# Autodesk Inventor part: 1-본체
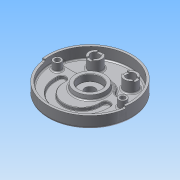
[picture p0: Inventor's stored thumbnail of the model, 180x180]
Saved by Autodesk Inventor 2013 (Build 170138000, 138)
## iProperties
Created: 2015-06
Part Number: 1-본체
Material: 알루미늄 6061
Document SubType Name: Modeling
Designer: Administrator
Density: 2.71 g/cm^3
Mass: 1076.47 g
Surface Area: 1039.69 cm^2
Volume: 397.221 cm^3
Author: Administrator
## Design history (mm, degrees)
sketch "스케치1"
  geometry: C1 r 95 at (0, 0); 1 further point
  constraints: 1 centre point, 1 coincident
  dimensions: "d0" = 190 diameter of C1
extrude "돌출1" new body sketch "스케치1" distance "d2" = 32; taper "d3" = 0 deg
sketch "스케치2"
  geometry: C1 r 95 at (0, 0) reference; C2 r 90 at (0, 0)
  constraints: 1 centre point, 1 coincident
  dimensions: "d4" = 180 diameter of C2
extrude "돌출2" cut sketch "스케치2" distance "d6" = 18; taper "d7" = 0 deg
sketch "스케치3"
  geometry: L1 (-95, 0)-(95, 0); L2 (0, 0)-(-94.075, -13.221); L3 (0, 0)-(94.075, -13.221); C1 r 90 at (0, 0) reference; A1 r 95 centre (0, 0) between (-95, 0) and (95, 0) reference; A2 r 90 centre (0, 0) between (-89.124, -12.526) and (89.124, -12.526); A3 r 95 centre (0, 0) between (-94.075, -13.221) and (94.075, -13.221)
  constraints: 8 point on circle, 6 end point, 3 coincident, 2 centre point, 2 concentric, 2 point on line, 1 horizontal, 1 midpoint
  dimensions: "d8" = 8 deg angle of L2 L1; "d10" = 8 deg angle of L3 L1
extrude "돌출3" cut sketch "스케치3" distance "d11" = 5; taper "d12" = 0 deg
sketch "스케치4"
  geometry: C1 r 95 at (0, 0) reference; C2 r 26 at (0, 0)
  constraints: 1 centre point, 1 coincident
  dimensions: "d13" = 52 diameter of C2
extrude "돌출4" join sketch "스케치4" distance "d15" = 12; taper "d16" = -15 deg
sketch "스케치5"
  geometry: L1 (90, 0)-(-90, 0); L2 (75.657, 16)-(45.033, 16); L3 (-45.033, 16)-(-75.657, 16); A1 r 90 centre (0, 0) between (-90, 0) and (90, 0) reference; A2 r 42 centre (0, 0) between (36.373, 21) and (-36.373, 21); A3 r 10 centre (-75.657, 26) between (-75.657, 16) and (-85.114, 29.25); A4 r 10 centre (-45.033, 26) between (-45.033, 16) and (-36.373, 21); A5 r 10 centre (45.033, 26) between (45.033, 16) and (36.373, 21); A6 r 10 centre (75.657, 26) between (75.657, 16) and (85.114, 29.25); A7 r 90 centre (0, 0) between (89.124, -12.526) and (-89.124, -12.526) reference; A8 r 90 centre (0, 0) between (85.114, 29.25) and (-85.114, 29.25)
  constraints: 14 point on circle, 12 tangent, 6 centre point, 6 end point, 3 equal radius, 2 coincident, 2 parallel, 1 horizontal, 1 midpoint
  dimensions: "d17" = 84 diameter of A2; "d19" = 10 radius of A3; "d21" = 16 distance between parallel lines of L1 L3; "d22" = 90 radius of A8
extrude "돌출5" cut sketch "스케치5" distance "d23" = 7; taper "d24" = 0 deg
sketch "스케치6"
  geometry: C1 r 35 at (0, 0); A1 r 42 centre (0, 0) between (36.373, 21) and (-36.373, 21) reference
  constraints: 1 centre point, 1 coincident
  dimensions: "d25" = 70 diameter of C1
extrude "돌출6" join sketch "스케치6" distance "d27" = 10; taper "d28" = -10 deg
hole "구멍1" diameter "d31" = 23; stored, may be unused: countersink angle "d35" = 90 deg, drill point angle "d37" = 118 deg; dims "d29" = 10, "d30" = 10, "d32" = 6, "d33" = 50, "d34" = 15, "d36" = 8
sketch "스케치7"
  geometry: C1 r 35 at (0, 0) reference; C2 r 9 at (-74, 0); C3 r 9 at (74, 0); A1 r 42 centre (0, 0) between (36.373, 21) and (-36.373, 21) reference; A2 r 74 centre (0, 0) between (-74, 0) and (74, 0)
  constraints: 3 centre point, 2 horizontal alignment, 2 point on circle, 1 coincident, 1 equal radius
  dimensions: "d38" = 148 diameter of A2; "d40" = 18 diameter of C3
extrude "돌출7" join sketch "스케치7" stored distance "d41" = 10; taper "d42" = 0 deg
sketch "스케치8"
  geometry: L1 (-45.033, 16)-(-75.657, 16) reference; L2 (-59, -19)-(59, -19); L3 (-59, -14)-(59, -14); L4 (-59, -19)-(-59, -14); L5 (-41, -19)-(-41, -14); L6 (41, -19)-(41, -14); L7 (59, -19)-(59, -14); L8 (-50, -19)-(-50, -14); L9 (50, -19)-(50, -14); C1 r 35 at (0, 0) reference; A1 r 59 centre (0, -19) between (-59, -19) and (59, -19); A2 r 41 centre (0, -19) between (-41, -19) and (41, -19); A3 r 50 centre (0, -19) between (-50, -19) and (50, -19); 3 further points
  constraints: 16 end point, 8 point on line, 6 point on circle, 6 tangent, 5 coincident, 4 parallel, 4 perpendicular, 3 centre point, 2 horizontal alignment, 1 midpoint, 1 vertical alignment, 4 other
  dimensions: "d43" = 59 radius of A1; "d45" = 41 radius of A2; "d46" = 19 distance of A1.centre C1.centre; "d47" = 5 distance between parallel lines of L2 L3; "d48" = 50 radius of A3
extrude "돌출8" cut sketch "스케치8" distance "d49" = 7; taper "d50" = 0 deg
sketch "스케치9"
  geometry: C1 r 15 at (-40, 52); C2 r 15 at (40, 52); C3 r 9 at (74, 0) reference; A1 r 90 centre (0, 0) between (85.114, 29.25) and (-85.114, 29.25) reference
  constraints: 2 centre point, 1 equal radius, 1 horizontal alignment
  dimensions: "d51" = 52 vertical distance of C3.centre C2.centre; "d52" = 30 diameter of C1; "d53" = 80 distance of C2.centre C1.centre; "d54" = 40 horizontal distance of A1.centre C1.centre
extrude "돌출9" join sketch "스케치9" stored distance "d55" = 7; taper "d56" = 0 deg
hole "구멍2" diameter "d68" = 20; stored, may be unused: countersink angle "d72" = 90 deg, drill point angle "d74" = 118 deg; dims "d66" = 10, "d67" = 10, "d69" = 6, "d70" = 50, "d71" = 15, "d73" = 8
hole "구멍3" diameter "d77" = 20; stored, may be unused: countersink angle "d81" = 90 deg, drill point angle "d83" = 118 deg; dims "d75" = 10, "d76" = 10, "d78" = 6, "d79" = 50, "d80" = 15, "d82" = 8
sketch "스케치10"
  geometry: L1 (6, -16)-(-6, -16); L2 (-6, -16)-(-6, 16); L3 (-6, 16)-(6, 16); L4 (6, 16)-(6, -16); L5 (6, -16)-(-6, 16); L6 (-6, -16)-(6, 16); L7 (64, 6)-(96, 6); L8 (96, 6)-(96, -6); L9 (96, -6)-(64, -6); L10 (64, -6)-(64, 6); L11 (64, 6)-(96, -6); L12 (96, 6)-(64, -6); C1 r 15 at (0, 0) reference; C2 r 15 at (80, 0) reference; 1 further point
  constraints: 24 end point, 4 midpoint, 4 parallel, 2 horizontal, 2 perpendicular
  dimensions: "d57" = 12 distance of L2.end L3.end; "d61" = 32 distance of L3.end L1.start; "d62" = 32 distance of L7.start L7.end; "d63" = 12 distance of L7.end L8.end
extrude "돌출10" cut sketch "스케치10" distance "d64" = 3; taper "d65" = 0 deg
sketch "스케치11"
  geometry: C1 r 26 at (0, 0) reference; C2 r 95 at (0, 0) reference; A1 r 74 centre (0, 0) between (-74, 0) and (74, 0)
  constraints: 2 horizontal alignment, 2 point on circle, 1 centre point, 1 coincident
  dimensions: "d84" = 148 diameter of A1
hole "구멍4" sketch "스케치11" at (-74, 0), (74, 0) diameter "d86" = 11; stored, may be unused: countersink angle "d90" = 90 deg, drill point angle "d92" = 118 deg; dims "d87" = 6, "d88" = 18, "d89" = 11, "d91" = 8
sketch "스케치12"
  geometry: C1 r 95 at (0, 0) reference; C2 r 68 at (0, 0)
  constraints: 1 centre point, 1 coincident, 1 other
  dimensions: "d93" = 136 diameter of C2
feature "엠보싱1" sketch "스케치12" dims "d95" = 0.5, "d96" = 0
chamfer "모따기1" distance "d97" = 1; stored, may be unused: second distance "d98" = 2, angle "d99" = 45 deg
fillet "모깎기1" dims "d100" = 0.3, "d101" = 1, "d102" = 3, "d103" = 5
node "솔리드1"
node "투영된 루프1"
other parameters: "d20" = 16
